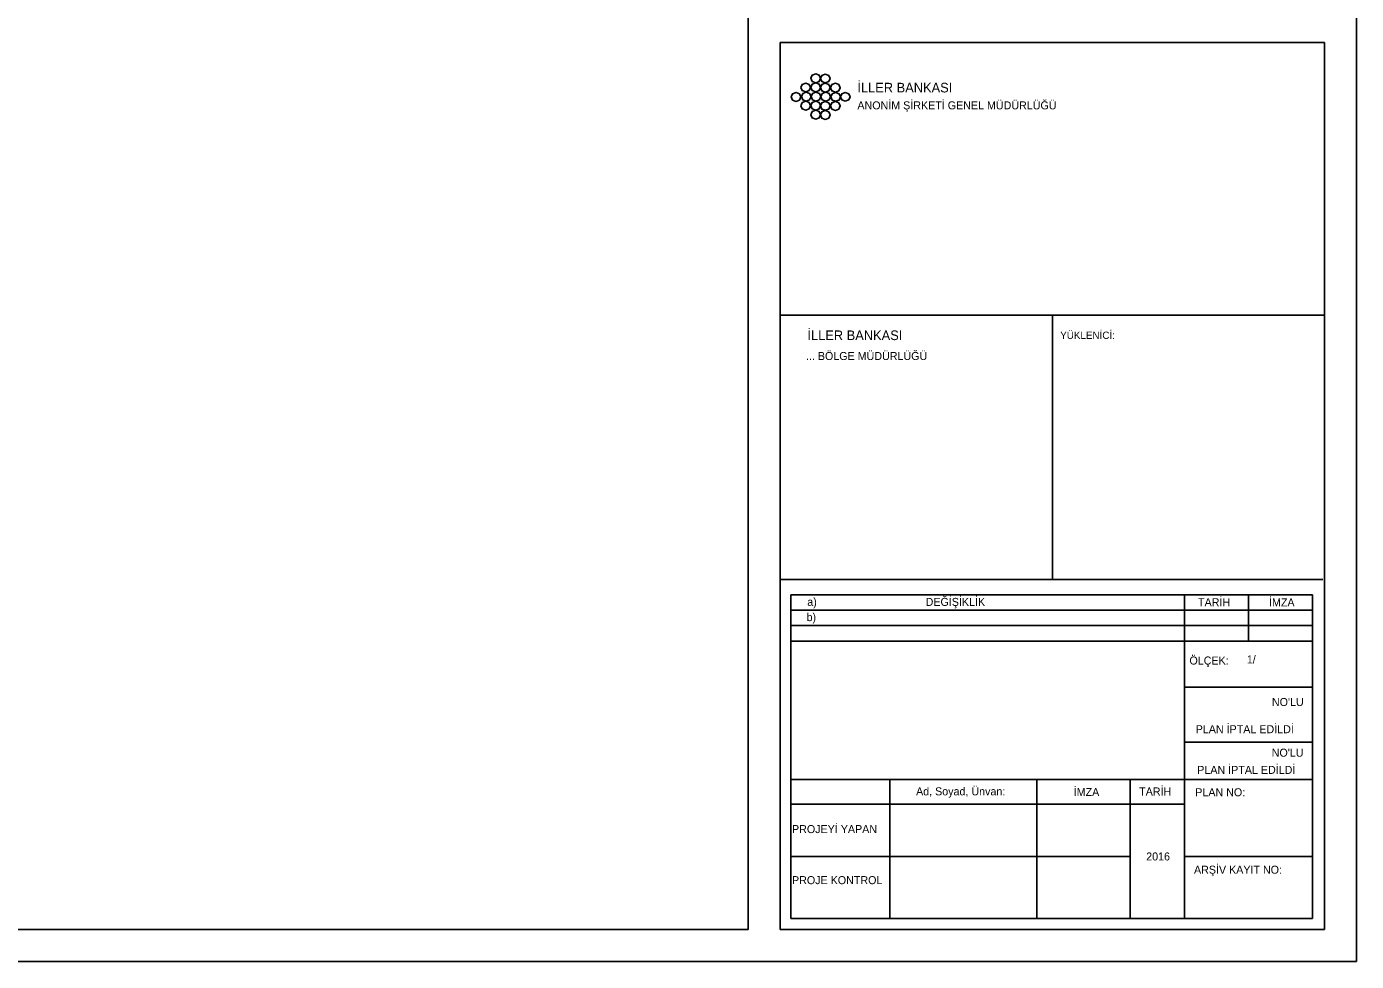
# Model space of a CAD drawing. Extents: x -10 to 821, y -10 to 550.
# Drawn here: x 405.5 to 821, y -10 to 282 of the extents above; entities that cross this region are included whole.
import ezdxf

# ---------------------------------------------------------------- set-up
doc = ezdxf.new("R2010")
doc.units = 0
for name, color, linetype in [('Baslik', 7, 'Continuous'), ('Level 50', 7, 'Continuous'), ('Level 51', 7, 'Continuous'), ('Level 53', 7, 'Continuous')]:
    doc.layers.add(name, color=color, linetype=linetype)

msp = doc.modelspace()

# ---------------------------------------------------------------- linework, layer by layer
at = {"layer": 'Baslik'}
for p, q in [((641, 191.88), (811, 191.88)), ((726, 109.32), (726, 191.88)), ((807.33, 109.32), (641, 109.32)), ((810.48, 109.32), (807.33, 109.32)), ((807.33, 104.51), (644.31, 104.51)), ((644.31, 3.37), (644.31, 104.51)), ((767.33, 3.37), (767.33, 104.51)), ((787.33, 90.08), (787.33, 104.51)), ((807.33, 104.51), (807.33, 3.37)), ((807.33, 99.7), (644.31, 99.7)), ((807.33, 94.89), (644.31, 94.89)), ((807.33, 90.08), (644.31, 90.08)), ((807.33, 75.65), (767.33, 75.65)), ((807.33, 58.53), (767.33, 58.53)), ((807.33, 46.8), (644.31, 46.8)), ((675.2, 3.37), (675.2, 46.8)), ((721.17, 3.37), (721.17, 46.8)), ((750.33, 3.37), (750.33, 46.8)), ((767.33, 39.11), (644.31, 39.11)), ((750.33, 22.76), (644.31, 22.76)), ((807.33, 22.76), (767.33, 22.76)), ((807.33, 3.37), (644.31, 3.37))]:
    msp.add_line(p, q, dxfattribs=at)
for points in [[(653.59, 265.86), (653.14, 264.88), (652.07, 264.47), (651, 264.88), (650.55, 265.86), (651, 266.84), (652.07, 267.25), (653.14, 266.84)], [(653.53, 265.79), (653.97, 266.77), (655.04, 267.18), (656.12, 266.77), (656.56, 265.79), (656.12, 264.8), (655.04, 264.4), (653.97, 264.8)], [(647.42, 262.97), (647.86, 263.95), (648.94, 264.36), (650.01, 263.95), (650.45, 262.97), (650.01, 261.99), (648.94, 261.58), (647.86, 261.99)], [(653.59, 263.01), (653.14, 262.03), (652.07, 261.62), (651, 262.03), (650.55, 263.01), (651, 263.99), (652.07, 264.4), (653.14, 263.99)], [(653.53, 262.94), (653.97, 263.92), (655.04, 264.33), (656.12, 263.92), (656.56, 262.94), (656.12, 261.95), (655.04, 261.55), (653.97, 261.95)], [(659.27, 263.9), (659.72, 262.92), (659.27, 261.93), (658.2, 261.53), (657.13, 261.93), (656.68, 262.92), (657.13, 263.9), (658.2, 264.31)], [(646.99, 259.06), (645.92, 258.65), (644.84, 259.06), (644.4, 260.04), (644.84, 261.02), (645.92, 261.43), (646.99, 261.02), (647.43, 260.04)], [(647.42, 257.27), (647.86, 258.26), (648.94, 258.66), (650.01, 258.26), (650.45, 257.27), (650.01, 256.29), (648.94, 255.88), (647.86, 256.29)], [(648.02, 261.1), (649.09, 261.51), (650.16, 261.1), (650.6, 260.12), (650.16, 259.13), (649.09, 258.73), (648.02, 259.13), (647.57, 260.12)], [(653.59, 257.31), (653.14, 256.33), (652.07, 255.92), (651, 256.33), (650.55, 257.31), (651, 258.3), (652.07, 258.7), (653.14, 258.3)], [(652.12, 261.51), (653.2, 261.1), (653.64, 260.12), (653.2, 259.14), (652.12, 258.73), (651.05, 259.14), (650.61, 260.12), (651.05, 261.1)], [(653.53, 257.24), (653.97, 258.22), (655.04, 258.63), (656.12, 258.22), (656.56, 257.24), (656.12, 256.26), (655.04, 255.85), (653.97, 256.26)], [(653.67, 260.11), (654.11, 261.1), (655.19, 261.5), (656.26, 261.1), (656.7, 260.11), (656.26, 259.13), (655.19, 258.72), (654.11, 259.13)], [(659.27, 258.2), (659.72, 257.22), (659.27, 256.24), (658.2, 255.83), (657.13, 256.24), (656.68, 257.22), (657.13, 258.2), (658.2, 258.61)], [(657.21, 261.03), (658.28, 261.44), (659.35, 261.03), (659.8, 260.05), (659.35, 259.07), (658.28, 258.66), (657.21, 259.07), (656.77, 260.05)], [(661.31, 258.67), (660.24, 259.08), (659.79, 260.06), (660.24, 261.05), (661.31, 261.45), (662.38, 261.05), (662.82, 260.06), (662.38, 259.08)], [(653.59, 254.47), (653.14, 253.48), (652.07, 253.08), (651, 253.48), (650.55, 254.47), (651, 255.45), (652.07, 255.86), (653.14, 255.45)], [(653.53, 254.39), (653.97, 255.38), (655.04, 255.78), (656.12, 255.38), (656.56, 254.39), (656.12, 253.41), (655.04, 253), (653.97, 253.41)]]:
    msp.add_lwpolyline(points, close=True, dxfattribs=at)
for points in [[(653.59, 265.86), (653.14, 264.88), (652.07, 264.47), (651, 264.88), (650.55, 265.86), (651, 266.84), (652.07, 267.25), (653.14, 266.84), (653.59, 265.86)], [(653.53, 265.79), (653.97, 266.77), (655.04, 267.18), (656.12, 266.77), (656.56, 265.79), (656.12, 264.8), (655.04, 264.4), (653.97, 264.8), (653.53, 265.79)], [(647.42, 262.97), (647.86, 263.95), (648.94, 264.36), (650.01, 263.95), (650.45, 262.97), (650.01, 261.99), (648.94, 261.58), (647.86, 261.99), (647.42, 262.97)], [(653.59, 263.01), (653.14, 262.03), (652.07, 261.62), (651, 262.03), (650.55, 263.01), (651, 263.99), (652.07, 264.4), (653.14, 263.99), (653.59, 263.01)], [(653.53, 262.94), (653.97, 263.92), (655.04, 264.33), (656.12, 263.92), (656.56, 262.94), (656.12, 261.95), (655.04, 261.55), (653.97, 261.95), (653.53, 262.94)], [(659.27, 263.9), (659.72, 262.92), (659.27, 261.93), (658.2, 261.53), (657.13, 261.93), (656.68, 262.92), (657.13, 263.9), (658.2, 264.31), (659.27, 263.9)], [(646.99, 259.06), (645.92, 258.65), (644.84, 259.06), (644.4, 260.04), (644.84, 261.02), (645.92, 261.43), (646.99, 261.02), (647.43, 260.04), (646.99, 259.06)], [(647.42, 257.27), (647.86, 258.26), (648.94, 258.66), (650.01, 258.26), (650.45, 257.27), (650.01, 256.29), (648.94, 255.88), (647.86, 256.29), (647.42, 257.27)], [(648.02, 261.1), (649.09, 261.51), (650.16, 261.1), (650.6, 260.12), (650.16, 259.13), (649.09, 258.73), (648.02, 259.13), (647.57, 260.12), (648.02, 261.1)], [(653.59, 257.31), (653.14, 256.33), (652.07, 255.92), (651, 256.33), (650.55, 257.31), (651, 258.3), (652.07, 258.7), (653.14, 258.3), (653.59, 257.31)], [(652.12, 261.51), (653.2, 261.1), (653.64, 260.12), (653.2, 259.14), (652.12, 258.73), (651.05, 259.14), (650.61, 260.12), (651.05, 261.1), (652.12, 261.51)], [(653.53, 257.24), (653.97, 258.22), (655.04, 258.63), (656.12, 258.22), (656.56, 257.24), (656.12, 256.26), (655.04, 255.85), (653.97, 256.26), (653.53, 257.24)], [(653.67, 260.11), (654.11, 261.1), (655.19, 261.5), (656.26, 261.1), (656.7, 260.11), (656.26, 259.13), (655.19, 258.72), (654.11, 259.13), (653.67, 260.11)], [(659.27, 258.2), (659.72, 257.22), (659.27, 256.24), (658.2, 255.83), (657.13, 256.24), (656.68, 257.22), (657.13, 258.2), (658.2, 258.61), (659.27, 258.2)], [(657.21, 261.03), (658.28, 261.44), (659.35, 261.03), (659.8, 260.05), (659.35, 259.07), (658.28, 258.66), (657.21, 259.07), (656.77, 260.05), (657.21, 261.03)], [(661.31, 258.67), (660.24, 259.08), (659.79, 260.06), (660.24, 261.05), (661.31, 261.45), (662.38, 261.05), (662.82, 260.06), (662.38, 259.08), (661.31, 258.67)], [(653.59, 254.47), (653.14, 253.48), (652.07, 253.08), (651, 253.48), (650.55, 254.47), (651, 255.45), (652.07, 255.86), (653.14, 255.45), (653.59, 254.47)], [(653.53, 254.39), (653.97, 255.38), (655.04, 255.78), (656.12, 255.38), (656.56, 254.39), (656.12, 253.41), (655.04, 253), (653.97, 253.41), (653.53, 254.39)]]:
    msp.add_lwpolyline(points, dxfattribs=at)
at = {"layer": 'Level 50'}
msp.add_lwpolyline([(0, 0), (631, 0), (631, 540), (0, 540)], close=True, dxfattribs=at)
at = {"layer": 'Level 51'}
msp.add_lwpolyline([(-10, -10), (821, -10), (821, 550), (-10, 550)], close=True, dxfattribs=at)
at = {"layer": 'Level 53'}
msp.add_lwpolyline([(641, 0), (811, 0), (811, 277), (641, 277)], close=True, dxfattribs=at)

# ---------------------------------------------------------------- texts
at = {"layer": 'Baslik'}
for s, height, p in [('İLLER BANKASI', 3, (665.08, 261.44)), ('ANONİM ŞİRKETİ GENEL MÜDÜRLÜĞÜ', 2.5, (665.08, 256.15)), ('İLLER BANKASI', 3, (649.47, 184.08)), ('YÜKLENİCİ:', 2.3, (728.45, 184.43)), ('... BÖLGE MÜDÜRLÜĞÜ', 2.5, (649.01, 177.85)), ('DEĞİŞİKLİK', 2.5, (686.41, 101.05)), ('TARİH', 2.5, (771.52, 100.93)), ('İMZA', 2.5, (793.7, 100.88)), ('a)', 2.5, (649.43, 101.05)), ('b)', 2.5, (649.21, 96.28)), ('ÖLÇEK:', 2.5, (768.84, 82.73)), ('1/     ', 2.5, (786.76, 83.06)), ("NO'LU", 2.5, (794.61, 69.77)), ('PLAN İPTAL EDİLDİ', 2.5, (770.79, 61.28)), ("NO'LU", 2.5, (794.54, 53.94)), ('PLAN İPTAL EDİLDİ', 2.5, (771.27, 48.58)), ('Ad, Soyad, Ünvan:', 2.5, (683.42, 41.87)), ('İMZA', 2.5, (732.67, 41.66)), ('TARİH', 2.5, (753.13, 41.82)), ('PLAN NO:', 2.5, (770.65, 41.58)), ('PROJEYİ YAPAN', 2.5, (644.66, 30.08)), ('2016', 2.5, (755.32, 21.53)), ('PROJE KONTROL', 2.5, (644.66, 14.13)), ('ARŞİV KAYIT NO:', 2.5, (770.26, 17.39))]:
    msp.add_text(s, height=height, dxfattribs=at).set_placement(p)

doc.saveas('drawing.dxf')
